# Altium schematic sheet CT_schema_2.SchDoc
size 293 x 134 mm
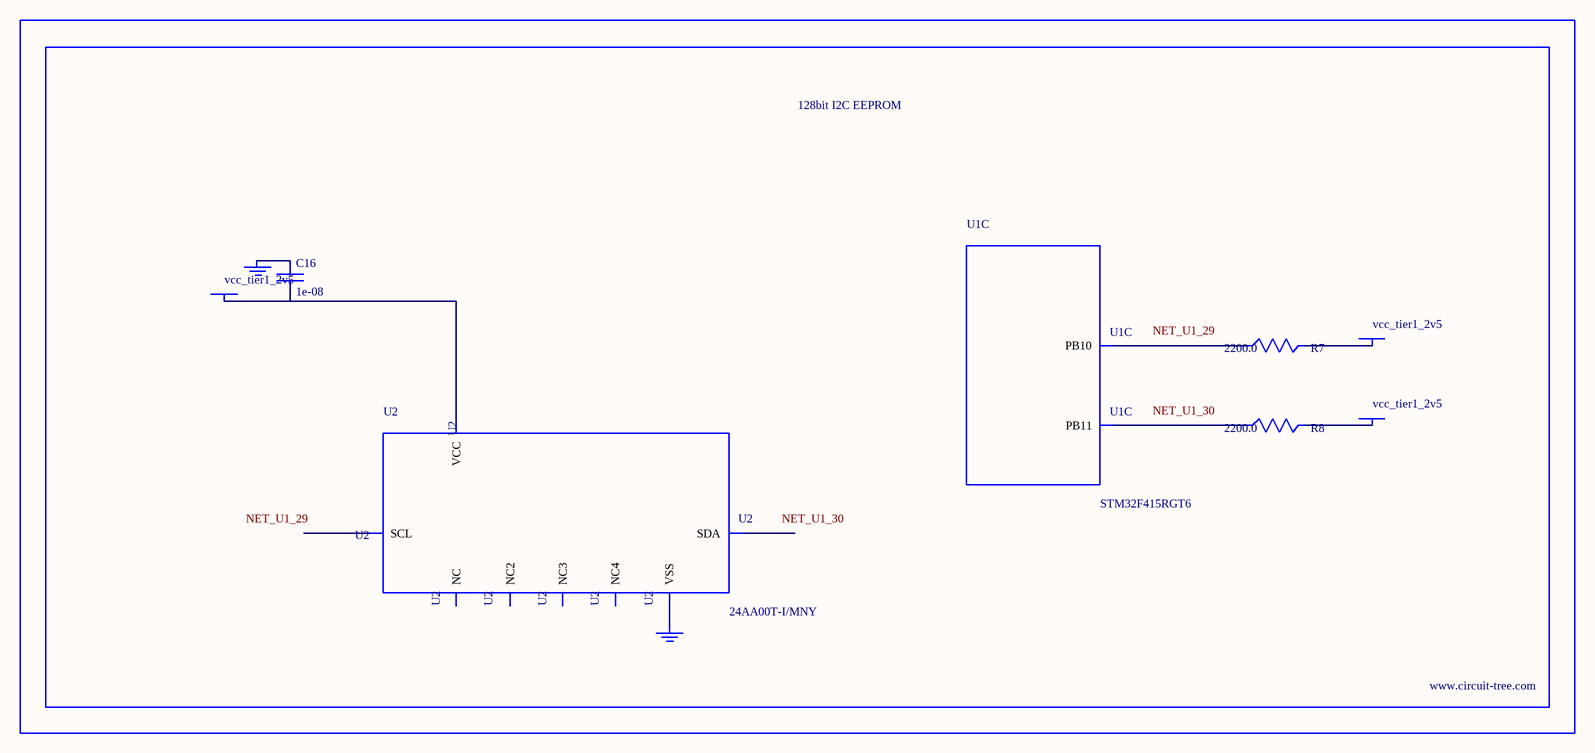
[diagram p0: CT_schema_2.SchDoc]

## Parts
BORDER1  (no value)
C16  1e-08  [C0402]
GND_INSTANCE_1_0  (no value)
GND_INSTANCE_1_1  (no value)
POWER_INSTANCE_1_0  vcc_tier1_2v5
POWER_INSTANCE_1_1  vcc_tier1_2v5
POWER_INSTANCE_1_2  vcc_tier1_2v5
R7  2200.0  [R0603]
R8  2200.0  [R0603]
U1  STM32F415RGT6  [LQFP64]  (part C of 7)
U2  24AA00T-I/MNY  [TDFN-8/6MM]

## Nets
NetC16_1: C16.1 GND_INSTANCE_1_0.0(GND)
NetC16_2: C16.2 POWER_INSTANCE_1_0.0(PWR) U2.8(VCC)
NetGND_INSTANCE_1_1_0: GND_INSTANCE_1_1.0(GND) U2.4(VSS)
NetPOWER_INSTANCE_1_1_0: POWER_INSTANCE_1_1.0(PWR) R7.2
NetPOWER_INSTANCE_1_2_0: POWER_INSTANCE_1_2.0(PWR) R8.2
NetR7_1: R7.1 U1.29(PB10)
NetR8_1: R8.1 U1.30(PB11)

Not connected (* = marked no-connect by the designer): U2 1(NC) 2(NC2) 3(NC3) 5(SDA) 6(SCL) 7(NC4)

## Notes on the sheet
- Labels drawn without touching a wire or pin: NET_U1_29, NET_U1_30

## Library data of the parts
BORDER1 = BORDER_PAGE1
C16 = C0402C103K3RAC
GND_INSTANCE_1_0 GND_INSTANCE_1_1 = GND
POWER_INSTANCE_1_0-POWER_INSTANCE_1_2 = PWR
R7 R8 = RC0603JR-072K2L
